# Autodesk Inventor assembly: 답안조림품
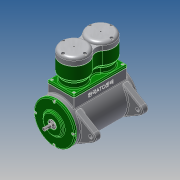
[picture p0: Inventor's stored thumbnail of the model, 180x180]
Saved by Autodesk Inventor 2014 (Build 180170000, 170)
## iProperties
Created: 2019-08
Part Number: 답안조림품
Document SubType Name: Assembly
Designer: kb542
Mass: 7629.5 g
Surface Area: 5241.59 cm^2
Volume: 2149.41 cm^3
Density: 3.54957 g/cm^3
Author: kb542
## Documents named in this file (18)
- C:\Users\kb542-11\Desktop\390804V1045\답안조림품.iam
- C:\Users\kb542-11\Desktop\390804V1045\본체.ipt
- C:\Users\kb542-11\Desktop\390804V1045\너트 M4.ipt
- C:\Users\kb542-11\Desktop\390804V1045\베어링 12 x 28 x 8.ipt
- C:\Users\kb542-11\Desktop\390804V1045\볼트 M4 x 8.ipt
- C:\Users\kb542-11\Desktop\390804V1045\볼트 M5 x 20.ipt
- C:\Users\kb542-11\Desktop\390804V1045\실린더 개스킷.ipt
- C:\Users\kb542-11\Desktop\390804V1045\실린더.ipt
- C:\Users\kb542-11\Desktop\390804V1045\실린더헤드 개스킷.ipt
- C:\Users\kb542-11\Desktop\390804V1045\실린더헤드.ipt
- C:\Users\kb542-11\Desktop\390804V1045\앞커버.ipt
- C:\Users\kb542-11\Desktop\390804V1045\오일 실 12 25 7.ipt
- C:\Users\kb542-11\Desktop\390804V1045\육각 머리 볼트 M4 x 16.ipt
- C:\Users\kb542-11\Desktop\390804V1045\커넥팅로드 엔드.ipt
- C:\Users\kb542-11\Desktop\390804V1045\커넥팅로드.ipt
- C:\Users\kb542-11\Desktop\390804V1045\크랭크축.ipt
- C:\Users\kb542-11\Desktop\390804V1045\피스톤.ipt
- C:\Users\kb542-11\Desktop\390804V1045\피스톤핀.ipt
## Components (4 placed, 2 different names)
1. 피스톤:1
2. 피스톤핀:1
3. 피스톤:2
4. 피스톤핀:3
## Named parameters: d41_d39 = 0, d42_d40 = 0, d43_d8 = 0, d44_d9 = 0, d45_d10 = 0, d46_d11 = 0, d47_d12 = 0, d48_d13 = 0, d49_d14 = 0, d50_d15 = 0, d51_d16 = 0, d52_d17 = 0, d53_d18 = 0, d54_d19 = 0, d55_d20 = 0, d56_d21 = 0
